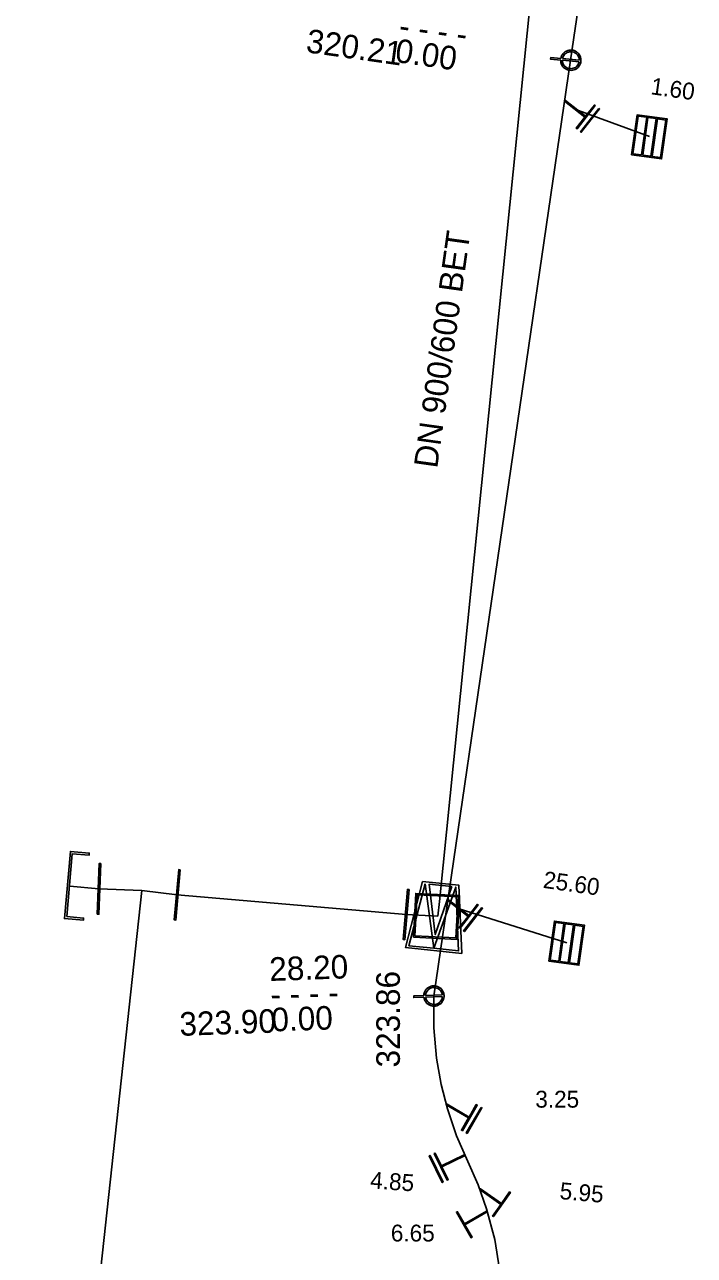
# Model space of a CAD drawing. Extents: x -817726 to -817387, y -1067947 to -1067694.
# Drawn here: x -817602.78 to -817582.92, y -1067870.57 to -1067834.06 of the extents above; entities that cross this region are included whole.
import ezdxf

# ---------------------------------------------------------------- set-up
doc = ezdxf.new("R2010")
doc.units = 0
doc.layers.add('Default', color=7, linetype='Continuous')
doc.layers.add('Level 0', color=7, linetype='Continuous')

msp = doc.modelspace()

# ---------------------------------------------------------------- linework, layer by layer
at = {"layer": 'Default'}
for points in [[(-817586.885, -1067835.111), (-817587.184, -1067835.084), (-817587.18, -1067835.035), (-817586.881, -1067835.062)], [(-817586.339, -1067835.158), (-817586.834, -1067835.115)], [(-817586.83, -1067835.066), (-817586.334, -1067835.109)], [(-817586.74, -1067836.31), (-817586.146, -1067836.775), (-817585.884, -1067836.441), (-817585.86, -1067836.459), (-817586.401, -1067837.15), (-817586.425, -1067837.132), (-817586.164, -1067836.799), (-817586.767, -1067836.327), (-817586.765, -1067836.306), (-817586.74, -1067836.31)], [(-817585.756, -1067836.54), (-817585.733, -1067836.558), (-817586.274, -1067837.25), (-817586.297, -1067837.232), (-817585.756, -1067836.54)], [(-817584.782, -1067837.917), (-817584.616, -1067836.729), (-817583.724, -1067836.854), (-817583.891, -1067838.042), (-817584.782, -1067837.917)], [(-817584.49, -1067837.92), (-817584.334, -1067836.806), (-817584.584, -1067836.771), (-817584.741, -1067837.885), (-817584.49, -1067837.92)], [(-817584.453, -1067837.926), (-817584.208, -1067837.96), (-817584.052, -1067836.846), (-817584.297, -1067836.812), (-817584.453, -1067837.926)], [(-817584.171, -1067837.965), (-817583.923, -1067838), (-817583.766, -1067836.886), (-817584.015, -1067836.851), (-817584.171, -1067837.965)], [(-817601.53, -1067860.521), (-817601.032, -1067860.565), (-817601.037, -1067860.627), (-817601.598, -1067860.578), (-817601.423, -1067858.586), (-817600.863, -1067858.635), (-817600.868, -1067858.697), (-817601.366, -1067858.653), (-817601.53, -1067860.521)], [(-817600.525, -1067858.948), (-817600.578, -1067860.447), (-817600.625, -1067860.445), (-817600.572, -1067858.946), (-817600.525, -1067858.948)], [(-817598.164, -1067859.129), (-817598.295, -1067860.623), (-817598.342, -1067860.619), (-817598.211, -1067859.125), (-817598.164, -1067859.129)], [(-817591.377, -1067859.713), (-817591.508, -1067861.207), (-817591.555, -1067861.203), (-817591.424, -1067859.709), (-817591.377, -1067859.713)], [(-817590.987, -1067859.476), (-817589.901, -1067859.591), (-817589.819, -1067861.61), (-817591.488, -1067861.435), (-817590.987, -1067859.476)], [(-817590.905, -1067859.548), (-817591.383, -1067861.383), (-817590.649, -1067861.46), (-817590.905, -1067859.548)], [(-817590.116, -1067859.631), (-817590.788, -1067859.56), (-817590.605, -1067861.053), (-817590.116, -1067859.631)], [(-817590.647, -1067861.46), (-817589.911, -1067861.538), (-817589.996, -1067859.643), (-817590.647, -1067861.46)], [(-817589.951, -1067861.195), (-817591.249, -1067861.127), (-817591.181, -1067859.829), (-817589.883, -1067859.897), (-817589.951, -1067861.195)], [(-817589.926, -1067859.936), (-817591.143, -1067859.872), (-817591.206, -1067861.089), (-817589.989, -1067861.153), (-817589.926, -1067859.936)], [(-817590.207, -1067860.023), (-817589.613, -1067860.488), (-817589.351, -1067860.154), (-817589.327, -1067860.172), (-817589.868, -1067860.863), (-817589.892, -1067860.845), (-817589.631, -1067860.512), (-817590.234, -1067860.04), (-817590.232, -1067860.019), (-817590.207, -1067860.023)], [(-817589.223, -1067860.253), (-817589.2, -1067860.271), (-817589.741, -1067860.963), (-817589.764, -1067860.945), (-817589.223, -1067860.253)], [(-817587.236, -1067861.839), (-817587.07, -1067860.651), (-817586.178, -1067860.776), (-817586.345, -1067861.964), (-817587.236, -1067861.839)], [(-817586.944, -1067861.842), (-817586.788, -1067860.728), (-817587.038, -1067860.693), (-817587.195, -1067861.807), (-817586.944, -1067861.842)], [(-817586.907, -1067861.848), (-817586.662, -1067861.882), (-817586.506, -1067860.768), (-817586.751, -1067860.734), (-817586.907, -1067861.848)], [(-817586.625, -1067861.887), (-817586.377, -1067861.922), (-817586.22, -1067860.808), (-817586.469, -1067860.773), (-817586.625, -1067861.887)], [(-817590.941, -1067862.91), (-817591.242, -1067862.921), (-817591.244, -1067862.871), (-817590.943, -1067862.861)], [(-817590.892, -1067862.859), (-817590.395, -1067862.842)], [(-817590.393, -1067862.891), (-817590.891, -1067862.908)], [(-817590.253, -1067866.087), (-817589.599, -1067866.465), (-817589.387, -1067866.097), (-817589.361, -1067866.112), (-817589.8, -1067866.872), (-817589.826, -1067866.857), (-817589.614, -1067866.491), (-817590.278, -1067866.107), (-817590.278, -1067866.087), (-817590.253, -1067866.087)], [(-817589.246, -1067866.178), (-817589.221, -1067866.192), (-817589.661, -1067866.953), (-817589.686, -1067866.938), (-817589.246, -1067866.178)], [(-817590.37, -1067868.395), (-817590.395, -1067868.408), (-817590.781, -1067867.619), (-817590.755, -1067867.606), (-817590.37, -1067868.395)], [(-817589.72, -1067867.587), (-817589.721, -1067867.608), (-817590.41, -1067867.944), (-817590.224, -1067868.324), (-817590.251, -1067868.337), (-817590.636, -1067867.548), (-817590.609, -1067867.535), (-817590.423, -1067867.917), (-817589.745, -1067867.585), (-817589.72, -1067867.587)], [(-817589.261, -1067868.599), (-817588.643, -1067869.033), (-817588.399, -1067868.685), (-817588.374, -1067868.702), (-817588.878, -1067869.421), (-817588.903, -1067869.404), (-817588.66, -1067869.058), (-817589.287, -1067868.617), (-817589.286, -1067868.597), (-817589.261, -1067868.599)], [(-817589.062, -1067869.259), (-817589.062, -1067869.28), (-817589.726, -1067869.664), (-817589.514, -1067870.03), (-817589.54, -1067870.045), (-817589.979, -1067869.284), (-817589.953, -1067869.27), (-817589.741, -1067869.637), (-817589.087, -1067869.259), (-817589.062, -1067869.259)]]:
    msp.add_lwpolyline(points, dxfattribs=at)
for points in [[(-817586.881, -1067835.062), (-817586.871, -1067835), (-817586.831, -1067834.941), (-817586.785, -1067834.873), (-817586.711, -1067834.84), (-817586.636, -1067834.807), (-817586.558, -1067834.813), (-817586.48, -1067834.82), (-817586.412, -1067834.867), (-817586.344, -1067834.913), (-817586.311, -1067834.988), (-817586.279, -1067835.062), (-817586.286, -1067835.138), (-817586.292, -1067835.214), (-817586.337, -1067835.282), (-817586.382, -1067835.35), (-817586.457, -1067835.384), (-817586.532, -1067835.418), (-817586.611, -1067835.411), (-817586.688, -1067835.404), (-817586.756, -1067835.359), (-817586.824, -1067835.313), (-817586.857, -1067835.238), (-817586.886, -1067835.173), (-817586.885, -1067835.111)], [(-817586.334, -1067835.109), (-817586.334, -1067835.062), (-817586.357, -1067835.008), (-817586.384, -1067834.946), (-817586.441, -1067834.907), (-817586.498, -1067834.869), (-817586.563, -1067834.863), (-817586.627, -1067834.857), (-817586.689, -1067834.885), (-817586.751, -1067834.912), (-817586.789, -1067834.969), (-817586.822, -1067835.017), (-817586.83, -1067835.066)], [(-817586.834, -1067835.115), (-817586.835, -1067835.164), (-817586.811, -1067835.218), (-817586.783, -1067835.28), (-817586.727, -1067835.318), (-817586.671, -1067835.356), (-817586.606, -1067835.361), (-817586.542, -1067835.367), (-817586.479, -1067835.339), (-817586.416, -1067835.31), (-817586.379, -1067835.254), (-817586.347, -1067835.205), (-817586.339, -1067835.158)], [(-817590.943, -1067862.861), (-817590.941, -1067862.799), (-817590.908, -1067862.735), (-817590.872, -1067862.662), (-817590.802, -1067862.62), (-817590.731, -1067862.578), (-817590.654, -1067862.575), (-817590.575, -1067862.573), (-817590.502, -1067862.61), (-817590.428, -1067862.648), (-817590.387, -1067862.718), (-817590.346, -1067862.788), (-817590.343, -1067862.865), (-817590.341, -1067862.94), (-817590.377, -1067863.013), (-817590.413, -1067863.086), (-817590.484, -1067863.129), (-817590.554, -1067863.172), (-817590.633, -1067863.175), (-817590.711, -1067863.178), (-817590.783, -1067863.141), (-817590.856, -1067863.104), (-817590.898, -1067863.033), (-817590.935, -1067862.972), (-817590.941, -1067862.91)], [(-817590.395, -1067862.842), (-817590.401, -1067862.794), (-817590.43, -1067862.744), (-817590.464, -1067862.685), (-817590.526, -1067862.654), (-817590.587, -1067862.623), (-817590.652, -1067862.625), (-817590.717, -1067862.627), (-817590.775, -1067862.662), (-817590.833, -1067862.697), (-817590.864, -1067862.758), (-817590.89, -1067862.81), (-817590.892, -1067862.859)], [(-817590.891, -1067862.908), (-817590.885, -1067862.957), (-817590.855, -1067863.008), (-817590.82, -1067863.066), (-817590.76, -1067863.097), (-817590.699, -1067863.127), (-817590.634, -1067863.125), (-817590.569, -1067863.123), (-817590.511, -1067863.087), (-817590.452, -1067863.051), (-817590.422, -1067862.99), (-817590.396, -1067862.939), (-817590.393, -1067862.891)]]:
    msp.add_open_spline(points, degree=3, dxfattribs=at)
at = {"layer": 'Level 0'}
for p, q in [((-817586.59, -1067835.112), (-817583.98, -1067817.406)), ((-817590.48, -1067860.072), (-817587.403, -1067829.638)), ((-817590.649, -1067862.876), (-817586.59, -1067835.112)), ((-817586.461, -1067836.564), (-817586.765, -1067836.312)), ((-817584.25, -1067837.379), (-817586.461, -1067836.564)), ((-817600.577, -1067859.697), (-817601.444, -1067859.621)), ((-817599.301, -1067859.748), (-817600.577, -1067859.697)), ((-817602.78, -1067891.735), (-817599.301, -1067859.748)), ((-817599.301, -1067859.748), (-817598.255, -1067859.875)), ((-817598.255, -1067859.875), (-817591.468, -1067860.459)), ((-817590.524, -1067860.51), (-817590.48, -1067860.072)), ((-817589.926, -1067860.276), (-817590.232, -1067860.024)), ((-817586.704, -1067861.301), (-817589.926, -1067860.276)), ((-817591.468, -1067860.459), (-817590.524, -1067860.51)), ((-817590.646, -1067863.824), (-817590.648, -1067862.875)), ((-817590.567, -1067864.716), (-817590.646, -1067863.824)), ((-817590.43, -1067865.497), (-817590.567, -1067864.716)), ((-817590.244, -1067866.227), (-817590.43, -1067865.497)), ((-817589.971, -1067867.023), (-817590.244, -1067866.227)), ((-817589.639, -1067867.78), (-817589.971, -1067867.023)), ((-817589.333, -1067868.474), (-817589.639, -1067867.78)), ((-817589.08, -1067869.186), (-817589.333, -1067868.474)), ((-817588.842, -1067870.097), (-817589.08, -1067869.186)), ((-817588.697, -1067870.975), (-817588.842, -1067870.097))]:
    msp.add_line(p, q, dxfattribs=at)

# ---------------------------------------------------------------- texts
for s, height, rotation, p in [('- - - -', 0.7, 352, (-817591.71, -1067834.42)), ('320.21', 0.7, 352, (-817594.461, -1067834.873)), ('0.00', 0.7, 352, (-817591.82, -1067835.162)), (' 1.60', 0.5, 352, (-817584.42, -1067836.093)), ('DN 900/600 BET', 0.7, 82, (-817590.547, -1067847.24)), ('25.60', 0.5, 352, (-817587.427, -1067859.663)), ('28.20', 0.7, 2, (-817595.514, -1067862.431)), ('323.86', 0.7, 90, (-817591.653, -1067864.995)), ('- - - -', 0.7, 2, (-817595.482, -1067863.18)), ('323.90', 0.7, 2, (-817598.177, -1067864.059)), ('0.00', 0.7, 2, (-817595.451, -1067863.929)), (' 4.85', 0.5, 356, (-817592.731, -1067868.569)), (' 5.95', 0.5, 355, (-817587.115, -1067868.881))]:
    msp.add_text(s, height=height, rotation=rotation, dxfattribs=at).set_placement(p)
for s, p in [(' 3.25', (-817587.824, -1067866.187)), (' 6.65', (-817592.107, -1067870.158))]:
    msp.add_text(s, height=0.5, dxfattribs=at).set_placement(p)

doc.saveas('drawing.dxf')
